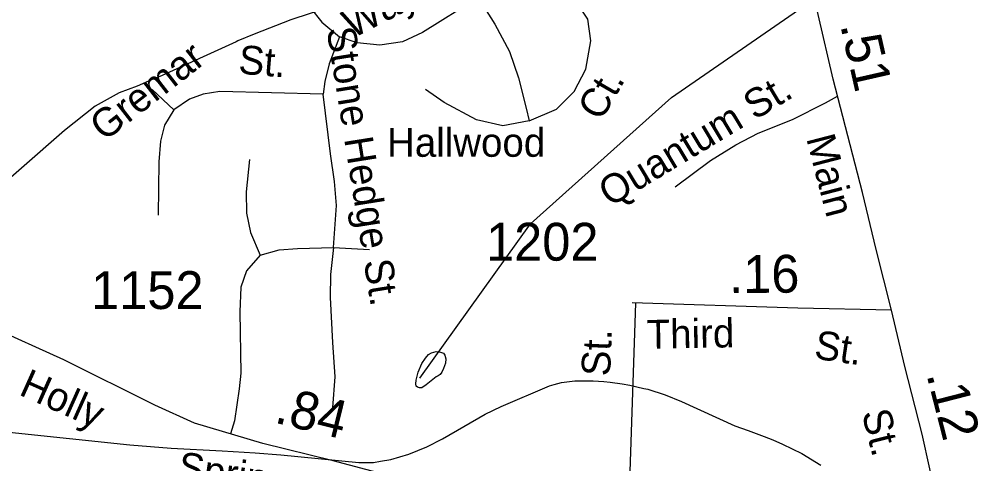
# Model space of a CAD drawing. Extents: x 2001466 to 2224147, y 644118 to 847247.
# Drawn here: x 2046197 to 2049368, y 693432 to 694901 of the extents above; entities that cross this region are included whole.
import ezdxf

# ---------------------------------------------------------------- set-up
doc = ezdxf.new("R2010")
doc.units = 0
for name, color, linetype in [('Exist Hydrographic Misc Water Feature', 7, 'Continuous'), ('Exist Road Non-System Type 51', 7, 'Continuous'), ('Exist Road Non-System Type 51 Label', 7, 'Continuous'), ('Exist Road Primary NC Attributed', 7, 'Continuous'), ('Exist Road Primary NC Label', 7, 'Continuous'), ('Exist Road Primary NC Service Mileage Hundredths English Label', 7, 'Continuous'), ('Exist Road Secondary Mileage Hundredths English Label', 7, 'Continuous'), ('Exist Road Secondary Type 51 Attributed', 7, 'Continuous'), ('Exist Road Secondary Type 51 Label', 7, 'Continuous'), ('Exist Road Secondary Type 51 Number Label', 7, 'Continuous')]:
    doc.layers.add(name, color=color, linetype=linetype)

msp = doc.modelspace()

# ---------------------------------------------------------------- linework, layer by layer
at = {"layer": 'Exist Hydrographic Misc Water Feature'}
for p, q in [((2046919.5, 694829.1), (2046914.2, 694826.8)), ((2048033.8, 693705.7), (2048039.1, 693706.3)), ((2047368, 693436.5), (2047390.7, 693440.4)), ((2048783.2, 693465.6), (2048846.2, 693428.1))]:
    msp.add_line(p, q, dxfattribs=at)
for points in [[(2047521.1, 693714.6), (2047887.1, 694225.5), (2048353.2, 694642.6), (2048943.2, 695050.5), (2048993.2, 695167.6), (2049139.2, 696355.9)], [(2047350.3, 694983.7), (2047095.2, 694899.3), (2046973.2, 694852.1), (2046919.5, 694829.1)], [(2047350.3, 694983.7), (2047095.2, 694899.3), (2046973.2, 694852.1), (2046919.5, 694829.1)], [(2046914.2, 694826.8), (2046669.1, 694715.5), (2046634.7, 694700.7)], [(2046914.2, 694826.8), (2046669.1, 694715.5), (2046634.7, 694700.7)], [(2046634.7, 694700.7), (2046587.1, 694680), (2046557.2, 694668.6)], [(2046634.7, 694700.7), (2046587.1, 694680), (2046557.2, 694668.6)], [(2046557.2, 694668.6), (2046527.2, 694657.3), (2046448.3, 694613.3), (2046346.4, 694533.7)], [(2046557.2, 694668.6), (2046527.2, 694657.3), (2046448.3, 694613.3), (2046346.4, 694533.7)], [(2046346.4, 694533.7), (2046052.3, 694276.9), (2045993.3, 694221.9), (2045954.7, 694178.8)], [(2046346.4, 694533.7), (2046052.3, 694276.9), (2045993.3, 694221.9), (2045954.7, 694178.8)], [(2047599.5, 693797.3), (2047603.6, 693791), (2047607.5, 693779), (2047605.6, 693765.1), (2047599.5, 693747), (2047593.3, 693734.9), (2047587.8, 693727.2), (2047581.6, 693722.9), (2047575.3, 693719), (2047541.6, 693692.8), (2047527.7, 693682.8), (2047519.5, 693682.8), (2047513.5, 693684.9), (2047509.4, 693688.8), (2047507.4, 693696.8), (2047509.4, 693708.7), (2047515.6, 693734.9), (2047527.5, 693763.2), (2047539.4, 693780.8), (2047549.4, 693793.1), (2047559.3, 693798.9), (2047575.3, 693803), (2047589.4, 693801.2), (2047599.5, 693797.3)], [(2047736.4, 693596), (2047790.2, 693621.8), (2047950.1, 693689.7), (2047965.1, 693694.2)], [(2047736.4, 693596), (2047790.2, 693621.8), (2047950.1, 693689.7), (2047965.1, 693694.2)], [(2047965.1, 693694.2), (2047989.1, 693701.1), (2048033.8, 693705.7)], [(2047965.1, 693694.2), (2047989.1, 693701.1), (2048033.8, 693705.7)], [(2048039.1, 693706.3), (2048094.2, 693706.2), (2048128.7, 693703.5)], [(2048039.1, 693706.3), (2048094.2, 693706.2), (2048128.7, 693703.5)], [(2048128.7, 693703.5), (2048150.2, 693701.9), (2048189.6, 693696)], [(2048128.7, 693703.5), (2048150.2, 693701.9), (2048189.6, 693696)], [(2048189.6, 693696), (2048215.2, 693692.2), (2048261.6, 693681.3)], [(2048189.6, 693696), (2048215.2, 693692.2), (2048261.6, 693681.3)], [(2048261.6, 693681.3), (2048274.9, 693678.2), (2048332.3, 693659.8)], [(2048332.3, 693659.8), (2048386.2, 693638), (2048562.2, 693558), (2048605.6, 693542.1)], [(2048332.3, 693659.8), (2048386.2, 693638), (2048562.2, 693558), (2048605.6, 693542.1)], [(2047544.1, 693488), (2047596, 693514.2), (2047736.4, 693596)], [(2046122.5, 693541.9), (2046163.9, 693536.3), (2046563.1, 693495.1), (2046699.1, 693484.1), (2046867.8, 693474.4)], [(2046122.5, 693541.9), (2046163.9, 693536.3), (2046563.1, 693495.1), (2046699.1, 693484.1), (2046867.8, 693474.4)], [(2048605.6, 693542.1), (2048659.2, 693522.5), (2048687.3, 693510.9)], [(2048605.6, 693542.1), (2048659.2, 693522.5), (2048687.3, 693510.9)], [(2048687.3, 693510.9), (2048719.2, 693497.5), (2048783.2, 693465.6)], [(2048687.3, 693510.9), (2048719.2, 693497.5), (2048783.2, 693465.6)], [(2046867.8, 693474.4), (2046977.1, 693468.1), (2047062.2, 693461.7)], [(2046867.8, 693474.4), (2046977.1, 693468.1), (2047062.2, 693461.7)], [(2047390.7, 693440.4), (2047425.2, 693446.5), (2047485.2, 693464.2), (2047544.1, 693488)], [(2047390.7, 693440.4), (2047425.2, 693446.5), (2047485.2, 693464.2), (2047544.1, 693488)], [(2047062.2, 693461.7), (2047319.2, 693436.1), (2047368, 693436.5)], [(2047062.2, 693461.7), (2047319.2, 693436.1), (2047368, 693436.5)]]:
    msp.add_lwpolyline(points, dxfattribs=at)
at = {"layer": 'Exist Road Non-System Type 51'}
for points in [[(2047129.1, 694997.8), (2047158.2, 694939.6), (2047196.9, 694891.2), (2047255.3, 694842.5)], [(2047713.5, 694972.3), (2047529.6, 694857), (2047463.4, 694826.3), (2047389.2, 694815), (2047313.4, 694823.1), (2047255.3, 694842.5)], [(2047713.5, 694972.3), (2047769.3, 694884.8), (2047817.7, 694794.3), (2047846.8, 694707.2), (2047872.6, 694607.1), (2047882.3, 694565.1)], [(2047882.3, 694565.1), (2047972.6, 694603.8), (2048030.7, 694662), (2048069.4, 694736.2), (2048085.6, 694829.9), (2048075.9, 694900.9), (2048027.5, 694975.2)], [(2047255.3, 694842.5), (2047221.4, 694753.7), (2047206.9, 694695.5), (2047202, 694652.9)], [(2046708, 694601.2), (2046637, 694669.1)], [(2047202, 694652.9), (2046860, 694662.6), (2046805.1, 694652.9), (2046759.6, 694636.8), (2046708, 694601.2)], [(2047235.6, 694146.8), (2047245.3, 694285.6), (2047238.8, 694364.7), (2047225.9, 694456.8), (2047202, 694652.9)], [(2047882.3, 694565.1), (2047795.1, 694548.9), (2047708, 694568.3), (2047601.5, 694626.4), (2047540.2, 694668.4)], [(2048365, 694347.1), (2048481.2, 694434.3), (2048565.1, 694486), (2048639.3, 694524.7), (2048752.2, 694569.9), (2048861.9, 694624.8), (2048901.1, 694647.2)], [(2046708, 694601.2), (2046677.4, 694551.2), (2046664.5, 694497.9), (2046658, 694429.3), (2046656.4, 694253.3)], [(2046958.1, 694437.4), (2046946.8, 694330.8), (2046948.4, 694259.8), (2046961.3, 694196.8), (2046993.6, 694120.9)], [(2046993.6, 694120.9), (2047056.5, 694138.7), (2047116.2, 694143.5), (2047235.6, 694146.8)], [(2047235.6, 694146.8), (2047225.9, 694057.2), (2047224.3, 693981.3), (2047232.4, 693832.8), (2047240.4, 693719.7), (2047232.4, 693618)], [(2047235.6, 694146.8), (2047355, 694140.3)], [(2046993.6, 694120.9), (2046948.4, 694070.1), (2046929.1, 694015.2), (2046925.8, 693934.5), (2046929.1, 693731), (2046924.2, 693679.4), (2046908.1, 693574.4), (2046894.9, 693531)], [(2048233.8, 693963.2), (2048212.9, 693340.7)]]:
    msp.add_lwpolyline(points, dxfattribs=at)
at = {"layer": 'Exist Road Primary NC Attributed'}
for points in [[(2049079.7, 693939.7), (2049029.5, 694140.4), (2048984.1, 694328.4), (2048886.5, 694703.4), (2048837.9, 694916.8), (2048763.5, 695240), (2048738.2, 695420.7), (2048716.6, 695646.7), (2048722.9, 695789.3), (2048731.9, 695958.3), (2048744.5, 696126.3), (2048772.5, 696331.2), (2048823.7, 696714.6), (2048870.7, 697085.4), (2048902.9, 697417.1), (2048942.4, 697683.3)], [(2049231.7, 693300.7), (2049181, 693529.9), (2049123.5, 693753.8), (2049079.7, 693939.7)]]:
    msp.add_lwpolyline(points, dxfattribs=at)
at = {"layer": 'Exist Road Secondary Type 51 Attributed'}
for points in [[(2049231.7, 693300.7), (2048849.5, 693312.9), (2048310.1, 693331.9), (2047902.1, 693338.2), (2047659.3, 693353), (2047450.3, 693384.7), (2047234.9, 693441.7), (2047002.7, 693498.8), (2046776.8, 693566.4), (2046644.8, 693625.5), (2046345, 693775.5), (2046100.1, 693885.4), (2045759.2, 694003.7), (2045468.9, 694106.2), (2045017.3, 694290.1)], [(2049079.7, 693939.7), (2048769.8, 693946.7), (2048223, 693963.6)]]:
    msp.add_lwpolyline(points, dxfattribs=at)

# ---------------------------------------------------------------- texts
at = {"layer": 'Exist Road Non-System Type 51 Label'}
for s, rotation, p in [('Way', 27.191, (2047297.9, 694836)), ('Stone Hedge St.', 279.0866, (2047212.6, 694868.9)), ('Gremar', 37.8861, (2046478.2, 694495)), ('St.', 355.2346, (2046919.4, 694721.6)), ('Ct.', 59.9419, (2048120, 694561.2)), ('Quantum St.', 30.9959, (2048149.2, 694278.8)), (' St.', 87.6105, (2048148, 693684.9))]:
    msp.add_text(s, height=95, rotation=rotation, dxfattribs=at).set_placement(p)
msp.add_text('Hallwood', height=95, dxfattribs=at).set_placement((2047412.8, 694446.5))
at = {"layer": 'Exist Road Primary NC Label'}
for s, rotation, p in [('Main', 284.5837, (2048797.5, 694507.7)), (' St.', 284.0049, (2048972.4, 693635.1))]:
    msp.add_text(s, height=95, rotation=rotation, dxfattribs=at).set_placement(p)
at = {"layer": 'Exist Road Primary NC Service Mileage Hundredths English Label'}
for s, rotation, p in [('.51', 282.82, (2048910, 694881.7)), ('.12', 284.4076, (2049194.8, 693727.3))]:
    msp.add_text(s, height=125, rotation=rotation, dxfattribs=at).set_placement(p)
at = {"layer": 'Exist Road Secondary Mileage Hundredths English Label'}
for s, rotation, p in [('.16', 0.4549, (2048543.5, 693996)), ('.84', 346.1998, (2047036.9, 693568.9))]:
    msp.add_text(s, height=125, rotation=rotation, dxfattribs=at).set_placement(p)
at = {"layer": 'Exist Road Secondary Type 51 Label'}
for s, rotation, p in [('Third', 0.9632, (2048271.5, 693812.2)), (' St.', 351.6996, (2048786.4, 693785.3)), ('Holly', 335.8529, (2046192.5, 693661.8)), ('Springs', 351.3786, (2046717.5, 693379.1))]:
    msp.add_text(s, height=95, rotation=rotation, dxfattribs=at).set_placement(p)
at = {"layer": 'Exist Road Secondary Type 51 Number Label'}
for s, p in [('1202', (2047739.7, 694103.3)), ('1152', (2046434.5, 693943.5))]:
    msp.add_text(s, height=125, dxfattribs=at).set_placement(p)

doc.saveas('drawing.dxf')
